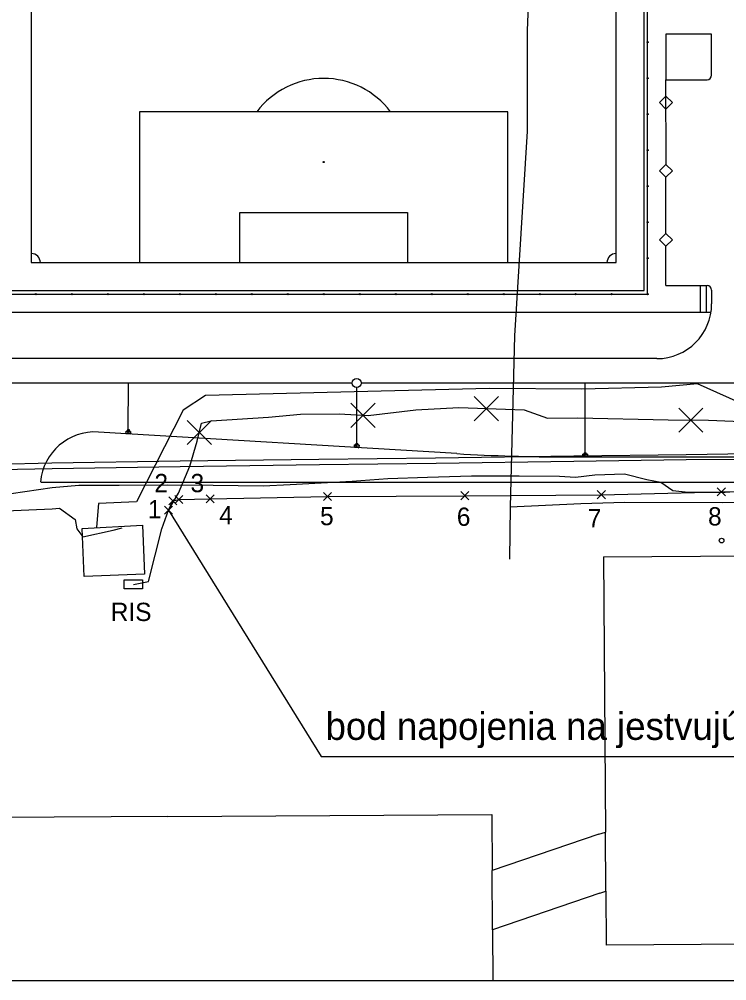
# Model space of a CAD drawing. Extents: x -264095 to -263675, y -1242370 to -1242073.
# Drawn here: x -264040.8 to -263963.4, y -1242369.5 to -1242264.4 of the extents above; entities that cross this region are included whole.
import ezdxf

# ---------------------------------------------------------------- set-up
doc = ezdxf.new("R2010")
doc.units = 0
for name, color, linetype in [('BODY', 7, 'Continuous'), ('KFA_2D_JESTVUJUCE_IS_DSP', 7, 'Continuous'), ('KFA_2D_SITUACIA_DSP', 7, 'Continuous'), ('ORANGE_KABEL_NOVA_TRASA', 7, 'Continuous'), ('POPIS', 7, 'Continuous'), ('Pripojka_NN_pre_ORANGE_vysielac_povodna_trasa', 7, 'Continuous'), ('Pripojka_NN_pre_ORANGE_vysielac_povodna_trasa_EL_SKRINA', 7, 'Continuous'), ('RAM_NA_TLAC_A3_1-1000', 7, 'Continuous')]:
    doc.layers.add(name, color=color, linetype=linetype)

msp = doc.modelspace()

# ---------------------------------------------------------------- linework, layer by layer
at = {"layer": 'BODY'}
for p, q in [((-264007.53, -1242316.99), (-264006.65, -1242316.11)), ((-264006.65, -1242316.99), (-264007.53, -1242316.11)), ((-263992.51, -1242316.91), (-263991.62, -1242316.02)), ((-263991.62, -1242316.91), (-263992.51, -1242316.02)), ((-263977.59, -1242316.8), (-263976.7, -1242315.91)), ((-263976.7, -1242316.8), (-263977.59, -1242315.91)), ((-263964.46, -1242316.5), (-263963.57, -1242315.61)), ((-263963.57, -1242316.5), (-263964.46, -1242315.61)), ((-264024.48, -1242317.48), (-264023.59, -1242316.6)), ((-264023.59, -1242317.48), (-264024.48, -1242316.6)), ((-264023.81, -1242317.32), (-264022.93, -1242316.44)), ((-264022.93, -1242317.32), (-264023.81, -1242316.44)), ((-264020.39, -1242317.27), (-264019.5, -1242316.38)), ((-264019.5, -1242317.27), (-264020.39, -1242316.38)), ((-264024.93, -1242318.5), (-264024.05, -1242317.62)), ((-264024.05, -1242318.5), (-264024.93, -1242317.62))]:
    msp.add_line(p, q, dxfattribs=at)
at = {"layer": 'KFA_2D_JESTVUJUCE_IS_DSP'}
for p, q in [((-263984.63, -1242252.16), (-263985.27, -1242265.6)), ((-263985.27, -1242265.6), (-263985.24, -1242276.61)), ((-263985.24, -1242276.61), (-263986.63, -1242298.98)), ((-263986.63, -1242298.98), (-263987.11, -1242317.68)), ((-263989.39, -1242304.73), (-264020.46, -1242305.5)), ((-263979.27, -1242304.82), (-263989.39, -1242304.73)), ((-263970.54, -1242304.6), (-263979.27, -1242304.82)), ((-263966.62, -1242304.22), (-263970.54, -1242304.6)), ((-263946.96, -1242313.09), (-263966.62, -1242304.22)), ((-264020.46, -1242305.5), (-264022.91, -1242307.11)), ((-264022.91, -1242307.11), (-264028.02, -1242317.15)), ((-263967.86, -1242311.99), (-263980.16, -1242312.16)), ((-263956.22, -1242311.84), (-263967.86, -1242311.99)), ((-264037.28, -1242312.92), (-264043.54, -1242313.06)), ((-264023.23, -1242312.7), (-264037.28, -1242312.92)), ((-264008.06, -1242312.52), (-264023.23, -1242312.7)), ((-264023.21, -1242313.28), (-264007.99, -1242313.07)), ((-263995.27, -1242312.37), (-264008.06, -1242312.52)), ((-264007.99, -1242313.07), (-263995.2, -1242312.9)), ((-263980.16, -1242312.16), (-263995.27, -1242312.37)), ((-263995.2, -1242312.9), (-263980.14, -1242312.68)), ((-263980.14, -1242312.68), (-263967.84, -1242312.51)), ((-263967.84, -1242312.51), (-263955.67, -1242312.42)), ((-264042.95, -1242313.61), (-264037.23, -1242313.51)), ((-264037.23, -1242313.51), (-264023.21, -1242313.28)), ((-263979.98, -1242314.43), (-263977.86, -1242314.19)), ((-263977.86, -1242314.19), (-263974.61, -1242314.09)), ((-263974.61, -1242314.09), (-263972.17, -1242314.7)), ((-264029.89, -1242315.32), (-264024.65, -1242315.29)), ((-264024.65, -1242315.29), (-264019.6, -1242315.33)), ((-264014.13, -1242315.41), (-264011.19, -1242315.25)), ((-264011.19, -1242315.25), (-264004.4, -1242314.87)), ((-264004.4, -1242314.87), (-264003.44, -1242314.8)), ((-264003.44, -1242314.8), (-264000.5, -1242314.59)), ((-264000.5, -1242314.59), (-263996.15, -1242314.45)), ((-263996.15, -1242314.45), (-263991.36, -1242314.31)), ((-263991.36, -1242314.31), (-263986.12, -1242314.3)), ((-263986.12, -1242314.3), (-263981.72, -1242314.33)), ((-263981.72, -1242314.33), (-263979.98, -1242314.43)), ((-263972.17, -1242314.7), (-263970.63, -1242314.99)), ((-263970.63, -1242314.99), (-263969.31, -1242315.89)), ((-264047.11, -1242317.03), (-264037.23, -1242315.56)), ((-264037.23, -1242315.56), (-264034.31, -1242315.31)), ((-264034.31, -1242315.31), (-264029.89, -1242315.32)), ((-264019.6, -1242315.33), (-264014.13, -1242315.41)), ((-263969.31, -1242315.89), (-263967.63, -1242316.08)), ((-263967.63, -1242316.08), (-263963.59, -1242316.09)), ((-263963.59, -1242316.09), (-263956.5, -1242315.61)), ((-264032.17, -1242317.31), (-264032.39, -1242319.93)), ((-264028.02, -1242317.15), (-264032.17, -1242317.31)), ((-263987.11, -1242317.68), (-263979.4, -1242317.34)), ((-263979.4, -1242317.34), (-263974.58, -1242317.17)), ((-263974.58, -1242317.17), (-263963.87, -1242317.22)), ((-263963.87, -1242317.22), (-263943.25, -1242316.73)), ((-264044.39, -1242318.22), (-264037.22, -1242317.89)), ((-264037.22, -1242317.89), (-264036.44, -1242317.83)), ((-264036.44, -1242317.83), (-264034.73, -1242319.08)), ((-263987.11, -1242317.68), (-263987.17, -1242323.4)), ((-264034.73, -1242319.08), (-264034.52, -1242320.11)), ((-264034.52, -1242320.11), (-264033.86, -1242320.96)), ((-264033.86, -1242320.96), (-264030.57, -1242320.23)), ((-264030.57, -1242320.23), (-264029.56, -1242320))]:
    msp.add_line(p, q, dxfattribs=at)
msp.add_circle((-263963.98, -1242321.38), 0.25, dxfattribs=at)
at = {"layer": 'KFA_2D_SITUACIA_DSP'}
for p, q in [((-264039.52, -1242190.98), (-264039.52, -1242290.98)), ((-263975.52, -1242290.98), (-263975.52, -1242190.98)), ((-263972.07, -1242294.43), (-263972.07, -1242255.06)), ((-263972.13, -1242266.87), (-263972.01, -1242266.87)), ((-263972.07, -1242266.93), (-263972.07, -1242266.81)), ((-263965.07, -1242265.98), (-263970.07, -1242265.98)), ((-263965.07, -1242270.48), (-263965.07, -1242265.98)), ((-263972.13, -1242270.81), (-263972.01, -1242270.81)), ((-263972.07, -1242270.87), (-263972.07, -1242270.75)), ((-263970.06, -1242280.24), (-263970.07, -1242270.98)), ((-263987.36, -1242274.48), (-264027.68, -1242274.48)), ((-264027.68, -1242274.48), (-264027.68, -1242290.98)), ((-263987.36, -1242290.98), (-263987.36, -1242274.48)), ((-263972.13, -1242274.74), (-263972.01, -1242274.74)), ((-263972.07, -1242274.8), (-263972.07, -1242274.68)), ((-263972.13, -1242278.68), (-263972.01, -1242278.68)), ((-263972.07, -1242278.74), (-263972.07, -1242278.62)), ((-263972.13, -1242282.62), (-263972.01, -1242282.62)), ((-263972.07, -1242282.68), (-263972.07, -1242282.56)), ((-263970.07, -1242287.78), (-263970.07, -1242281.65)), ((-264016.68, -1242290.98), (-264016.68, -1242285.48)), ((-264016.68, -1242285.48), (-263998.36, -1242285.48)), ((-263998.36, -1242285.48), (-263998.36, -1242290.98)), ((-263972.13, -1242286.56), (-263972.01, -1242286.56)), ((-263972.07, -1242286.62), (-263972.07, -1242286.5)), ((-263970.07, -1242293.48), (-263970.07, -1242289.19)), ((-264039.52, -1242290.98), (-263975.52, -1242290.98)), ((-263972.13, -1242290.49), (-263972.01, -1242290.49)), ((-263972.07, -1242290.55), (-263972.07, -1242290.43)), ((-263970.07, -1242293.48), (-263965.57, -1242293.48)), ((-263966.31, -1242293.48), (-263966.31, -1242296.43)), ((-263965.68, -1242293.48), (-263965.68, -1242296.43)), ((-263965.07, -1242293.98), (-263965.07, -1242295.48)), ((-264045.12, -1242294.43), (-263972.07, -1242294.43)), ((-264038.97, -1242294.43), (-264039.09, -1242294.43)), ((-264039.03, -1242294.49), (-264039.03, -1242294.37)), ((-264035.03, -1242294.43), (-264035.15, -1242294.43)), ((-264035.09, -1242294.49), (-264035.09, -1242294.37)), ((-264031.09, -1242294.43), (-264031.21, -1242294.43)), ((-264031.15, -1242294.49), (-264031.15, -1242294.37)), ((-264027.15, -1242294.43), (-264027.27, -1242294.43)), ((-264027.21, -1242294.49), (-264027.21, -1242294.37)), ((-264023.21, -1242294.43), (-264023.33, -1242294.43)), ((-264023.27, -1242294.49), (-264023.27, -1242294.37)), ((-264019.27, -1242294.43), (-264019.39, -1242294.43)), ((-264019.33, -1242294.49), (-264019.33, -1242294.37)), ((-264015.34, -1242294.43), (-264015.46, -1242294.43)), ((-264015.4, -1242294.49), (-264015.4, -1242294.37)), ((-264011.4, -1242294.43), (-264011.52, -1242294.43)), ((-264011.46, -1242294.49), (-264011.46, -1242294.37)), ((-264007.46, -1242294.43), (-264007.58, -1242294.43)), ((-264007.52, -1242294.49), (-264007.52, -1242294.37)), ((-264003.52, -1242294.43), (-264003.64, -1242294.43)), ((-264003.58, -1242294.49), (-264003.58, -1242294.37)), ((-263999.58, -1242294.43), (-263999.7, -1242294.43)), ((-263999.64, -1242294.49), (-263999.64, -1242294.37)), ((-263995.64, -1242294.43), (-263995.76, -1242294.43)), ((-263995.7, -1242294.49), (-263995.7, -1242294.37)), ((-263991.7, -1242294.43), (-263991.82, -1242294.43)), ((-263991.76, -1242294.49), (-263991.76, -1242294.37)), ((-263987.76, -1242294.43), (-263987.88, -1242294.43)), ((-263987.82, -1242294.49), (-263987.82, -1242294.37)), ((-263983.82, -1242294.43), (-263983.94, -1242294.43)), ((-263983.88, -1242294.49), (-263983.88, -1242294.37)), ((-263979.89, -1242294.43), (-263980.01, -1242294.43)), ((-263979.95, -1242294.49), (-263979.95, -1242294.37)), ((-263975.95, -1242294.43), (-263976.07, -1242294.43)), ((-263976.01, -1242294.49), (-263976.01, -1242294.37)), ((-263972.13, -1242294.43), (-263972.01, -1242294.43)), ((-263972.07, -1242294.49), (-263972.07, -1242294.37)), ((-263971.07, -1242301.48), (-264095.11, -1242301.48)), ((-264004.4, -1242304.15), (-264044.53, -1242304.15)), ((-264028.9, -1242309.22), (-264028.89, -1242304.15)), ((-264003.9, -1242310.72), (-264003.9, -1242304.65)), ((-263954.41, -1242304.15), (-264003.4, -1242304.15)), ((-263978.91, -1242311.74), (-263978.91, -1242304.15)), ((-263992.94, -1242311.87), (-264032.17, -1242309.51)), ((-264032.17, -1242309.51), (-264032.17, -1242309.51)), ((-264029.16, -1242309.69), (-264029.14, -1242309.41)), ((-264028.66, -1242309.72), (-264029.16, -1242309.69)), ((-264029.14, -1242309.41), (-264028.65, -1242309.44)), ((-264029.14, -1242309.41), (-264028.66, -1242309.72)), ((-264029.14, -1242309.41), (-264028.66, -1242309.72)), ((-264028.65, -1242309.44), (-264029.14, -1242309.41)), ((-264028.65, -1242309.44), (-264028.66, -1242309.72)), ((-264028.66, -1242309.72), (-264028.65, -1242309.44)), ((-264004.16, -1242311.2), (-264004.15, -1242310.91)), ((-264004.15, -1242310.91), (-264003.65, -1242310.94)), ((-264004.15, -1242310.91), (-264003.66, -1242311.23)), ((-264004.15, -1242310.91), (-264003.66, -1242311.23)), ((-264003.65, -1242310.94), (-264004.15, -1242310.91)), ((-264003.65, -1242310.94), (-264003.66, -1242311.23)), ((-264003.66, -1242311.23), (-264003.65, -1242310.94)), ((-264003.66, -1242311.23), (-264004.16, -1242311.2)), ((-263979.16, -1242311.94), (-263978.66, -1242311.94)), ((-263979.16, -1242312.23), (-263979.16, -1242311.94)), ((-263979.16, -1242311.94), (-263978.66, -1242312.23)), ((-263979.16, -1242311.94), (-263978.66, -1242312.23)), ((-263978.66, -1242311.94), (-263979.16, -1242311.94)), ((-263978.66, -1242311.94), (-263978.66, -1242312.23)), ((-263978.66, -1242312.23), (-263978.66, -1242311.94)), ((-263980.94, -1242312.23), (-263885.11, -1242312.23)), ((-263978.66, -1242312.23), (-263979.16, -1242312.23)), ((-264038.44, -1242314.98), (-263885.11, -1242314.98)), ((-264033.95, -1242320.06), (-264027.34, -1242319.71)), ((-264033.72, -1242325.32), (-264033.95, -1242320.06)), ((-264027.34, -1242319.71), (-264027.11, -1242325.04)), ((-263976.89, -1242323.14), (-263885.11, -1242322.54)), ((-263976.89, -1242323.14), (-263976.69, -1242353.26)), ((-264027.11, -1242325.04), (-264033.72, -1242325.32)), ((-264024.58, -1242351.56), (-264061.87, -1242351.8)), ((-264024.58, -1242351.56), (-263989.12, -1242351.34)), ((-263989.12, -1242351.34), (-263989.08, -1242357.47)), ((-263977.4, -1242353.5), (-263989.08, -1242357.47)), ((-263977.4, -1242353.5), (-263976.69, -1242353.26)), ((-263976.65, -1242359.72), (-263976.69, -1242353.26)), ((-263989.04, -1242363.95), (-263989.08, -1242357.47)), ((-263977.32, -1242359.95), (-263989.04, -1242363.95)), ((-263977.32, -1242359.95), (-263976.65, -1242359.72)), ((-263976.65, -1242359.72), (-263976.61, -1242365.64)), ((-263989.04, -1242363.95), (-263989.01, -1242369.53)), ((-263934.57, -1242365.37), (-263976.61, -1242365.64))]:
    msp.add_line(p, q, dxfattribs=at)
for points in [[(-264042.57, -1242294.03), (-263972.47, -1242294.03), (-263972.47, -1242187.93), (-264042.57, -1242187.93)], [(-263970.07, -1242272.78), (-263969.36, -1242273.48), (-263970.07, -1242274.19), (-263970.77, -1242273.48)], [(-263970.07, -1242280.24), (-263969.36, -1242280.94), (-263970.07, -1242281.65), (-263970.77, -1242280.94)], [(-263970.07, -1242287.78), (-263969.36, -1242288.48), (-263970.07, -1242289.19), (-263970.77, -1242288.48)]]:
    msp.add_lwpolyline(points, close=True, dxfattribs=at)
for points in [[(-263970.07, -1242265.98), (-263970.07, -1242270.98), (-263965.57, -1242270.98)], [(-263965.14, -1242296.43), (-264095.11, -1242296.43)]]:
    msp.add_lwpolyline(points, dxfattribs=at)
for centre, radius in [((-263972.07, -1242266.87), 0.06), ((-263972.07, -1242270.81), 0.06), ((-263972.07, -1242274.74), 0.06), ((-263972.07, -1242278.68), 0.06), ((-264007.52, -1242279.98), 0.06), ((-263972.07, -1242282.62), 0.06), ((-263972.07, -1242286.56), 0.06), ((-263972.07, -1242290.49), 0.06), ((-264039.03, -1242294.43), 0.06), ((-264035.09, -1242294.43), 0.06), ((-264031.15, -1242294.43), 0.06), ((-264027.21, -1242294.43), 0.06), ((-264023.27, -1242294.43), 0.06), ((-264019.33, -1242294.43), 0.06), ((-264015.4, -1242294.43), 0.06), ((-264011.46, -1242294.43), 0.06), ((-264007.52, -1242294.43), 0.06), ((-264003.58, -1242294.43), 0.06), ((-263999.64, -1242294.43), 0.06), ((-263995.7, -1242294.43), 0.06), ((-263991.76, -1242294.43), 0.06), ((-263987.82, -1242294.43), 0.06), ((-263983.88, -1242294.43), 0.06), ((-263979.95, -1242294.43), 0.06), ((-263976.01, -1242294.43), 0.06), ((-263972.07, -1242294.43), 0.06), ((-264003.9, -1242304.15), 0.5), ((-264028.89, -1242309.32), 0.1), ((-264003.9, -1242310.82), 0.1), ((-263978.91, -1242311.84), 0.1)]:
    msp.add_circle(centre, radius, dxfattribs=at)
for centre, radius, start, end in [((-264007.52, -1242279.98), 9.15, 36.9482, 143.0518), ((-263965.57, -1242270.48), 0.5, 270, 0), ((-264007.52, -1242279.98), 0.0303, 90, 270), ((-264007.52, -1242279.98), 0.0303, 270, 90), ((-264039.52, -1242290.98), 1, 0, 90), ((-263975.52, -1242290.98), 1, 90, 180), ((-263965.57, -1242293.98), 0.5, 0, 90), ((-263971.07, -1242295.48), 6, 270, 0), ((-264032.53, -1242315.5), 6, 86.5602, 175.0205), ((-263980.94, -1242112.23), 200, 266.5602, 270)]:
    msp.add_arc(centre, radius, start, end, dxfattribs=at)
at = {"layer": 'ORANGE_KABEL_NOVA_TRASA'}
msp.add_lwpolyline([(-264024.49, -1242318.06), (-264024.03, -1242317.04), (-264023.37, -1242316.88), (-264019.94, -1242316.82), (-264007.09, -1242316.55), (-263992.06, -1242316.47), (-263977.15, -1242316.36), (-263964.02, -1242316.05), (-263949.32, -1242315.78), (-263948.85, -1242315.55), (-263948.88, -1242313.34), (-263948.91, -1242263.22), (-263949.46, -1242259.66), (-263949.68, -1242246.61), (-263949.38, -1242192.16), (-263951.11, -1242181.25), (-263952.04, -1242175.2)], dxfattribs=at)
at = {"layer": 'POPIS'}
for p, q in [((-264024.49, -1242318.06), (-264007.78, -1242345)), ((-264007.78, -1242345), (-263924.8, -1242345))]:
    msp.add_line(p, q, dxfattribs=at)
at = {"layer": 'Pripojka_NN_pre_ORANGE_vysielac_povodna_trasa'}
for p, q in [((-263991.05, -1242308.27), (-263988.4, -1242305.61)), ((-263988.4, -1242308.27), (-263991.05, -1242305.61)), ((-264004.55, -1242309), (-264001.9, -1242306.34)), ((-264001.9, -1242309), (-264004.55, -1242306.34)), ((-263968.67, -1242309.53), (-263966.02, -1242306.88)), ((-263966.02, -1242309.53), (-263968.67, -1242306.88)), ((-264022.47, -1242310.88), (-264019.81, -1242308.23)), ((-264019.81, -1242310.88), (-264022.47, -1242308.23))]:
    msp.add_line(p, q, dxfattribs=at)
msp.add_lwpolyline([(-264028.34, -1242326.17), (-264026.68, -1242325.84), (-264025.24, -1242320.11), (-264024.49, -1242318.06), (-264023.39, -1242316.2), (-264022.16, -1242313.25), (-264021.37, -1242310.52), (-264020.9, -1242308.55), (-264019.83, -1242308.29), (-264013.56, -1242307.87), (-264010.05, -1242307.57), (-264005.83, -1242307.52), (-264002.65, -1242307.7), (-263997.42, -1242307.08), (-263992.74, -1242306.84), (-263985.59, -1242307.08), (-263983.02, -1242307.99), (-263979.72, -1242307.94), (-263969.81, -1242308.19), (-263965.43, -1242308.21), (-263960.91, -1242308.38)], dxfattribs=at)
at = {"layer": 'Pripojka_NN_pre_ORANGE_vysielac_povodna_trasa_EL_SKRINA'}
msp.add_lwpolyline([(-264029.34, -1242325.67), (-264027.34, -1242325.67), (-264027.34, -1242326.67), (-264029.34, -1242326.67)], close=True, dxfattribs=at)
at = {"layer": 'RAM_NA_TLAC_A3_1-1000'}
msp.add_lwpolyline([(-264095.11, -1242072.53), (-263675.11, -1242072.53), (-263675.11, -1242369.53), (-264095.11, -1242369.53)], close=True, dxfattribs=at)

# ---------------------------------------------------------------- texts
at = {"layer": 'BODY'}
for s, p in [('2', (-264026.04, -1242316.09)), ('3', (-264022.09, -1242316.09)), ('1', (-264026.76, -1242318.95)), ('4', (-264018.95, -1242319.59)), ('5', (-264007.92, -1242319.7)), ('6', (-263992.95, -1242319.77)), ('7', (-263978.62, -1242319.93)), ('8', (-263965.46, -1242319.73))]:
    msp.add_text(s, height=2, dxfattribs=at).set_placement(p)
at = {"layer": 'POPIS'}
msp.add_text('bod napojenia na jestvujúcu trasu - začiatok', height=3, dxfattribs=at).set_placement((-264007.32, -1242343.18))
at = {"layer": 'Pripojka_NN_pre_ORANGE_vysielac_povodna_trasa_EL_SKRINA'}
msp.add_text('RIS', height=2, dxfattribs=at).set_placement((-264030.82, -1242330.18))

doc.saveas('drawing.dxf')
